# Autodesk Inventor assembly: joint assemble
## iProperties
Author: chr
Created: 2002-03
Part Number: joint assemble
Document SubType Name: Assemblage
Designer: chr
Control State: 0
Master: False
Checked Out: False
PropertySet Name: Design Tracking Control
Shininess: 41.0
Angle Display Precision: 2
Document Length Units: 11269
Document Angle Units: 11283
Document Time Units: 11279
Document Mass Units: 11290
Document Length Units Precision: 3
Document Angle Units Precision: 2
Compacted: False
PropertySet Name: _Private Model Information
Density: 0.0
Volumn: 0.0
Area: 0.0
PropertySet Name: Model Information
